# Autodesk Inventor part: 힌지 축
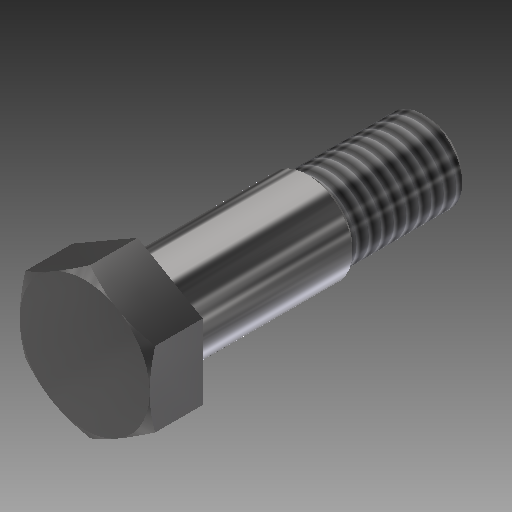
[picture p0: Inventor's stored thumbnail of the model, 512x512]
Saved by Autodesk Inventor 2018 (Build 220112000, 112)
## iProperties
Created: 2019-09
Part Number: 힌지 축
Material: 스테인리스강
Document SubType Name: Modeling
Designer: mduedu
Density: 8.08 g/cm^3
Appearance: 반광택
Mass: 19.8099 g
Surface Area: 13.175 cm^2
Volume: 2.45172 cm^3
Author: mduedu
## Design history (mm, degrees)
sketch "스케치1"
  geometry: C1 r 4 at (0, 0); 1 further point
  constraints: 1 centre point, 1 coincident
  dimensions: "d0" = 8 diameter of C1
extrude "돌출1" new body sketch "스케치1" distance "d1" = 29; taper "d2" = 0 deg
sketch "스케치2"
  geometry: C1 r 4.5 at (0, 0); 1 further point
  constraints: 1 centre point, 1 coincident
  dimensions: "d3" = 9 diameter of C1
extrude "돌출2" join sketch "스케치2" distance "d4" = 17.5; taper "d5" = 0 deg
sketch "스케치3"
  geometry: L1 (0, 7.506)-(6.5, 3.753); L2 (6.5, 3.753)-(6.5, -3.753); L3 (6.5, -3.753)-(0, -7.506); L4 (0, -7.506)-(-6.5, -3.753); L5 (-6.5, -3.753)-(-6.5, 3.753); L6 (-6.5, 3.753)-(0, 7.506); C1 r 6.5 at (0, 0); 2 further points
  constraints: 12 end point, 2 coincident, 1 centre point, 1 tangent, 1 vertical alignment, 13 other
  dimensions: "d6" = 6.5 radius of C1
extrude "돌출3" join sketch "스케치3" distance "d8" = 5.3; taper "d9" = 0 deg
sketch "스케치4"
  geometry: L1 (-4, 11.5)-(-4.5, 11.5) reference; L2 (-4.5, 11.5)-(-4.5, 29) reference; L3 (-4.5, 29)-(-7.506, 29) reference; L4 (-7.506, 29)-(-7.506, 34.3) reference; L5 (-7.506, 34.3)-(7.506, 34.3) reference; L6 (7.506, 34.3)-(7.506, 29) reference; L7 (7.506, 29)-(4.5, 29) reference; L8 (4.5, 29)-(4.5, 11.5) reference; L9 (4.5, 11.5)-(4, 11.5) reference; L10 (4, 11.5)-(4, 0) reference; L11 (4, 0)-(-4, 0) reference; L12 (-4, 0)-(-4, 11.5) reference; L13 (0, 0)-(0, 34.3); L14 (7.506, 34.3)-(7.506, 33.746); L15 (6.506, 34.3)-(7.506, 33.746); L16 (7.506, 34.3)-(6.506, 34.3); L17 (4.5, 29)-(4, 29); L18 (4, 29)-(4, 28.5); L19 (4, 28.5)-(4.5, 28.5); L20 (4.5, 28.5)-(4.5, 29)
  constraints: 16 end point, 2 parallel, 2 perpendicular, 2 point on line, 1 horizontal, 1 midpoint
  dimensions: "d10" = 1 distance of L5.end L15.start; "d11" = 29 deg angle of L15 L5; "d12" = 0.5 distance of L19.end L7.end; "d13" = 0.5 distance of L18.end L19.end
revolve "회전1" sketch "스케치4" stored, may be unused: angle "d14" = 90 deg
feature "스레드1" dims "d15" = 10, "d16" = 0
chamfer "모따기1" distance "d17" = 0.5; stored, may be unused: second distance "d18" = 2, angle "d19" = 45 deg
chamfer "모따기2" distance "d20" = 0.5; stored, may be unused: second distance "d21" = 2, angle "d22" = 45 deg
node "솔리드1"
node "절단 모서리 투영1"
